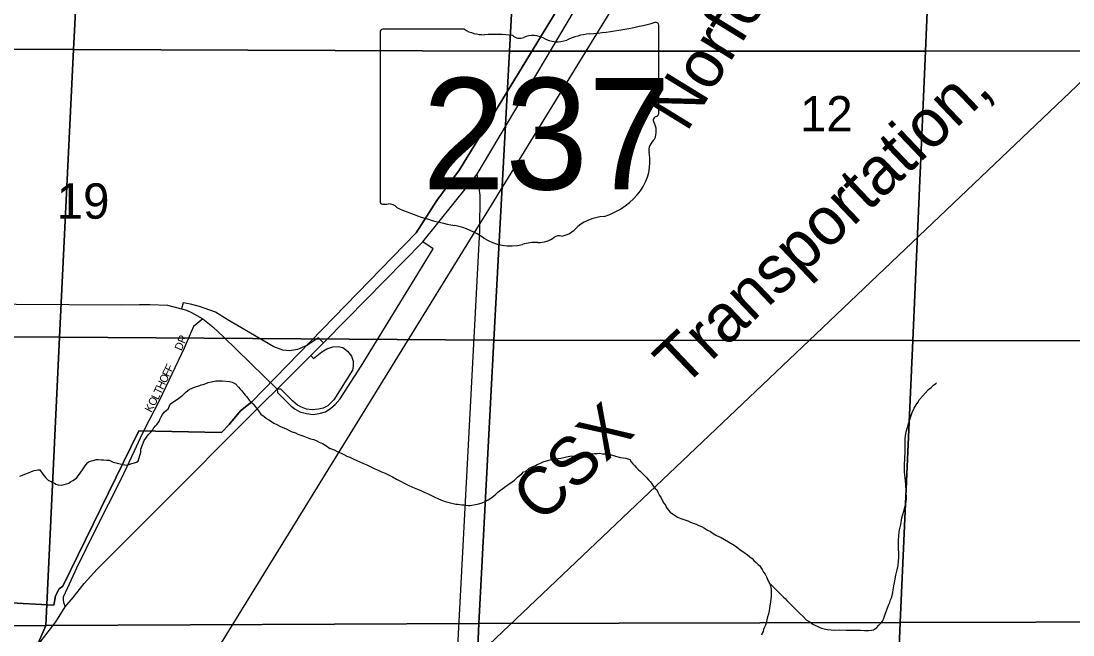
# Model space of a CAD drawing. Extents: x 2010165 to 2382125, y 1060529 to 1407316.
# Drawn here: x 2146157 to 2152727, y 1235609 to 1239445 of the extents above; entities that cross this region are included whole.
import ezdxf

# ---------------------------------------------------------------- set-up
doc = ezdxf.new("R2010")
doc.units = 0
for name, color, linetype in [('GM_X_City_Street', 7, 'Continuous'), ('GM_X_City_Street_Text', 7, 'Continuous'), ('GM_X_Corporation', 7, 'Continuous'), ('GM_X_Interchange_Ramps', 7, 'Continuous'), ('GM_X_Minor_River', 7, 'Continuous'), ('GM_X_Rail_Line', 7, 'Continuous'), ('GM_X_Rail_Line_Text', 7, 'Continuous'), ('GM_X_Section', 7, 'Continuous'), ('GM_X_Section_Text', 7, 'Continuous'), ('GM_X_State_Location', 7, 'Continuous'), ('GM_X_State_Route', 7, 'Continuous'), ('GM_X_State_Shield', 7, 'Continuous')]:
    doc.layers.add(name, color=color, linetype=linetype)

msp = doc.modelspace()

# ---------------------------------------------------------------- linework, layer by layer
at = {"layer": 'GM_X_City_Street'}
for points in [[(2148879.3, 1235417.3), (2149023.3, 1238135.7), (2149024.9, 1238357.3), (2149006, 1238487.7)], [(2144660.8, 1237692.8), (2145141.7, 1237682.9), (2146781.9, 1237671), (2146895.9, 1237673.3)], [(2146895.9, 1237673.3), (2146961.2, 1237674.6), (2147072.4, 1237669.7), (2147159, 1237647.3), (2147190.7, 1237637.5), (2147221, 1237624.8), (2147291.5, 1237584.5), (2147355.1, 1237533.5), (2147421.7, 1237471.6), (2147756.2, 1237145.5)], [(2147291.5, 1237584.5), (2147235.1, 1237535.5), (2147220.5, 1237503.5), (2147176.8, 1237401.6), (2147021.4, 1237075.5), (2146924.8, 1236885.7)], [(2146924.8, 1236885.7), (2146900.5, 1236837.9), (2146863.8, 1236758.1), (2146781.7, 1236585.3), (2146622, 1236267.8), (2146503.8, 1236026.5), (2146446.8, 1235902.8), (2146420.4, 1235844.7), (2146419.9, 1235826.8), (2146421.8, 1235814.4), (2146433.4, 1235784.8)]]:
    msp.add_lwpolyline(points, dxfattribs=at)
at = {"layer": 'GM_X_Corporation'}
for points in [[(2146055.1, 1235811.6), (2146361.7, 1235795.5), (2146372.7, 1235852.5), (2146394.6, 1235897.4), (2146419, 1235913.2), (2146892.4, 1236883.9), (2147408.3, 1236874.9), (2147457.8, 1236924.4), (2147528.5, 1237008.7), (2147599.3, 1237065.9), (2148624.8, 1238120.8), (2148753, 1238322.8), (2148895.2, 1238514.3), (2151697.2, 1243110.1)], [(2151697.2, 1243110.1), (2148895.2, 1238514.3), (2148753, 1238322.8), (2148624.8, 1238120.8), (2147599.3, 1237065.9), (2147528.5, 1237008.7), (2147457.8, 1236924.4), (2147408.3, 1236874.9), (2146892.4, 1236883.9), (2146419, 1235913.2), (2146394.6, 1235897.4), (2146372.7, 1235852.5), (2146361.7, 1235795.5), (2146055.1, 1235811.6)]]:
    msp.add_lwpolyline(points, dxfattribs=at)
at = {"layer": 'GM_X_Interchange_Ramps'}
for points in [[(2147756.2, 1237145.5), (2147758.3, 1237123.3), (2147843.4, 1237039.4), (2147869.9, 1237019.3), (2147899, 1237002.1), (2147940.3, 1236992), (2147981.5, 1236987.3), (2148019.8, 1236993.6), (2148059.4, 1237004), (2148091.8, 1237026.6), (2148118.7, 1237049.1), (2148149.5, 1237084), (2148174.8, 1237124.2), (2148281, 1237288.2), (2148730.9, 1238021), (2148667.3, 1238066.4)], [(2148045.6, 1237434.2), (2148015.3, 1237465.6), (2147941.1, 1237417.2), (2147884.1, 1237393.5), (2147833.9, 1237384.7), (2147791.2, 1237387.7), (2147736.5, 1237409.9), (2147444.1, 1237580.3), (2147371.3, 1237625.4), (2147272.1, 1237660.6), (2147215.3, 1237676.4), (2147169.3, 1237683.7), (2147159, 1237647.3)], [(2147966.1, 1237354.9), (2147983.9, 1237337), (2148036.6, 1237377.8), (2148067.7, 1237396.2), (2148104.4, 1237409.3), (2148138.7, 1237411.4), (2148167.6, 1237405.1), (2148196.9, 1237382.4), (2148220.8, 1237351.4), (2148231, 1237320), (2148231.7, 1237287.2), (2148228.1, 1237263.8), (2148111.3, 1237077.7), (2148073.7, 1237041.3), (2148043.8, 1237027), (2148015.2, 1237019.5), (2147975.5, 1237014.6), (2147939.8, 1237019.4), (2147909.3, 1237032.5), (2147883, 1237044.3), (2147852.3, 1237071), (2147778.7, 1237143.7), (2147756.2, 1237145.5)]]:
    msp.add_lwpolyline(points, dxfattribs=at)
at = {"layer": 'GM_X_Minor_River'}
for points in [[(2147139.9, 1237086), (2147153.8, 1237096.3), (2147163.7, 1237102.5), (2147179.4, 1237118.8), (2147189.3, 1237129.1), (2147207.1, 1237143.5), (2147229, 1237153.9), (2147246.9, 1237160.3), (2147260.9, 1237162.6), (2147272.9, 1237166.8), (2147282.8, 1237171), (2147294.8, 1237173.2), (2147310.8, 1237179.6), (2147326.7, 1237185.9), (2147346.7, 1237190.3), (2147372.6, 1237196.8), (2147392.7, 1237197.2), (2147414.8, 1237197.6), (2147459, 1237192.4), (2147475.1, 1237188.7), (2147487.3, 1237182.9), (2147497.4, 1237177.1), (2147515.9, 1237157.4), (2147526.1, 1237145.6), (2147536.4, 1237133.7), (2147548.7, 1237117.9), (2147556.9, 1237108), (2147565.1, 1237098.1), (2147573.3, 1237088.3), (2147581.6, 1237076.4), (2147591.8, 1237066.6), (2147608.1, 1237050.8), (2147616.4, 1237038.9), (2147626.7, 1237025.1), (2147641, 1237009.3), (2147655.4, 1236989.5), (2147675.8, 1236973.8), (2147690.1, 1236962.1), (2147704.3, 1236952.3), (2147720.5, 1236942.6), (2147736.8, 1236932.9), (2147755, 1236923.2), (2147773.2, 1236913.5), (2147791.4, 1236905.8), (2147809.6, 1236898.1), (2147825.8, 1236890.4), (2147844.1, 1236880.7), (2147870.3, 1236871.2), (2147886.5, 1236863.5), (2147904.7, 1236857.8), (2147922.9, 1236850.1), (2147943.1, 1236842.5), (2147965.3, 1236834.9), (2147985.5, 1236829.3), (2148003.7, 1236821.6), (2148019.9, 1236813.9), (2148040.1, 1236804.2), (2148060.4, 1236792.6), (2148082.8, 1236776.9), (2148113.1, 1236765.5), (2148135.4, 1236753.9), (2148155.6, 1236744.2), (2148173.8, 1236736.6), (2148192.1, 1236726.9), (2148210.3, 1236719.2), (2148230.5, 1236709.5), (2148295.3, 1236680.7), (2148317.5, 1236671.1), (2148345.9, 1236657.6), (2148366.1, 1236647.9), (2148388.4, 1236638.3), (2148408.6, 1236628.7), (2148430.9, 1236619.1), (2148455.2, 1236607.5), (2148477.5, 1236595.9), (2148501.8, 1236582.3), (2148526.1, 1236570.7), (2148550.4, 1236557.1), (2148574.7, 1236545.6), (2148601.1, 1236532), (2148633.4, 1236520.6), (2148657.7, 1236509), (2148679.9, 1236499.4), (2148700.2, 1236489.8), (2148720.4, 1236480.1), (2148740.7, 1236470.5), (2148760.9, 1236460.8), (2148783.2, 1236451.2), (2148805.4, 1236443.6), (2148823.6, 1236437.9), (2148837.7, 1236434.2), (2148855.8, 1236430.5), (2148871.9, 1236426.8), (2148886, 1236425.1), (2148898.1, 1236423.3), (2148910.1, 1236421.5), (2148924.2, 1236421.8), (2148934.3, 1236420), (2148952.4, 1236418.3), (2148962.4, 1236418.5), (2148972.4, 1236420.7)], [(2150831.6, 1235932.6), (2150895, 1235869.6), (2150907.3, 1235857.8), (2150919.5, 1235846), (2150929.8, 1235836.1), (2150940, 1235824.3), (2150954.3, 1235810.5), (2150968.6, 1235794.7), (2150987, 1235777), (2151003.4, 1235761.3), (2151023.8, 1235741.6), (2151042.2, 1235723.9), (2151060.6, 1235704.2), (2151083, 1235690.6), (2151101.3, 1235676.9), (2151115.5, 1235669.1), (2151129.6, 1235663.3), (2151141.8, 1235657.6), (2151155.9, 1235651.8), (2151174.1, 1235646.1), (2151194.2, 1235642.5), (2151216.3, 1235640.9), (2151238.4, 1235639.3), (2151270.5, 1235640), (2151312.7, 1235638.8), (2151344.8, 1235639.4), (2151374.9, 1235637.9), (2151401, 1235638.4), (2151425.1, 1235636.9), (2151449.2, 1235637.4), (2151469.2, 1235637.8), (2151481.2, 1235640), (2151501, 1235654.4), (2151514.8, 1235670.7), (2151528.5, 1235685.1), (2151538.4, 1235695.3), (2151544.2, 1235707.4), (2151551.8, 1235731.6), (2151574.7, 1235794.3), (2151582.4, 1235812.5), (2151588.1, 1235828.7), (2151593.9, 1235840.8), (2151597.6, 1235854.9), (2151601.3, 1235875.1), (2151605, 1235891.2), (2151608.6, 1235915.3), (2151614, 1235947.6), (2151621.4, 1235981.8), (2151628.8, 1236016.1), (2151634.3, 1236042.3), (2151637.8, 1236068.4), (2151639.4, 1236094.5), (2151638.9, 1236118.6), (2151638.4, 1236148.7), (2151637.5, 1236194.8), (2151638.8, 1236233), (2151644.2, 1236265.2), (2151651.6, 1236299.5), (2151658.9, 1236339.8), (2151670.2, 1236382.1), (2151679.6, 1236414.4), (2151685.2, 1236438.6), (2151686.7, 1236464.7), (2151686, 1236502.8), (2151683.1, 1236548.9), (2151678.3, 1236591), (2151675.6, 1236629.1), (2151675.3, 1236645.1), (2151675, 1236661.1), (2151674.6, 1236683.2), (2151676.3, 1236701.3), (2151677.9, 1236721.4), (2151679.5, 1236741.5), (2151679.1, 1236763.6), (2151678.7, 1236787.6), (2151678.2, 1236813.7), (2151679.9, 1236831.8), (2151681.4, 1236855.9), (2151685, 1236878.1), (2151692.6, 1236904.3), (2151700.2, 1236928.5), (2151705.8, 1236948.7), (2151713.4, 1236972.9), (2151722.9, 1236999.2), (2151734.5, 1237025.5), (2151748.2, 1237045.8), (2151757.9, 1237062.1), (2151769.6, 1237080.4), (2151824.6, 1237141.6), (2151840.4, 1237156), (2151856.2, 1237170.3), (2151870.1, 1237180.6), (2151874.4, 1237183.6)], [(2146149.5, 1236601.4), (2146165.5, 1236607.8), (2146181.4, 1236614.1), (2146203.3, 1236622.5), (2146223.2, 1236630.9), (2146239.2, 1236637.3), (2146249.2, 1236639.5), (2146261.2, 1236641.7), (2146275.2, 1236640), (2146293.8, 1236614.2), (2146310.2, 1236592.5), (2146328.6, 1236574.8), (2146342.8, 1236569), (2146355, 1236561.2), (2146365.1, 1236557.4), (2146375.2, 1236551.6), (2146389.3, 1236547.8), (2146407.5, 1236544.2), (2146425.4, 1236548.5), (2146441.4, 1236552.8), (2146455.4, 1236557.1), (2146465.3, 1236565.3), (2146481.2, 1236573.7), (2146503, 1236588.1), (2146540.1, 1236641), (2146553.8, 1236659.3), (2146563.6, 1236673.6), (2146571.4, 1236683.8), (2146583.3, 1236692), (2146597.3, 1236696.3), (2146607.3, 1236698.5), (2146625.2, 1236704.9), (2146639.3, 1236705.1), (2146659.4, 1236703.5), (2146671.4, 1236703.8), (2146693.5, 1236700.1), (2146707.6, 1236700.4), (2146731.9, 1236688.8), (2146760.1, 1236681.4), (2146784.3, 1236675.8), (2146804.4, 1236672.2), (2146818.5, 1236670.4), (2146848.4, 1236681.1), (2146866.4, 1236685.4), (2146878.4, 1236689.6), (2146888.3, 1236693.9), (2146905.3, 1236750.4), (2146905, 1236770.4), (2146926, 1236823), (2146951.5, 1236859.6), (2146967.2, 1236876), (2146977, 1236888.2), (2146986.8, 1236902.4), (2146996.6, 1236914.7), (2147004.4, 1236924.8), (2147020.1, 1236943.2), (2147023.9, 1236955.3), (2147031.7, 1236971.5), (2147041.4, 1236985.8), (2147051.2, 1237002), (2147067, 1237016.4), (2147076.9, 1237020.6), (2147088.4, 1237050.9), (2147118.1, 1237071.5), (2147139.9, 1237086)], [(2148972.4, 1236420.7), (2148996.4, 1236423.2), (2149016.4, 1236427.6), (2149036.3, 1236434), (2149056.2, 1236442.4), (2149074.1, 1236452.8), (2149092, 1236463.2), (2149107.8, 1236475.5), (2149121.6, 1236487.8), (2149135.4, 1236500.1), (2149151.2, 1236514.5), (2149167.1, 1236524.8), (2149184.9, 1236539.2), (2149196.8, 1236547.4), (2149224.5, 1236566), (2149238.4, 1236576.3), (2149258.1, 1236594.8), (2149270, 1236605), (2149283.8, 1236615.3), (2149295.6, 1236627.6), (2149307.6, 1236629.8), (2149331.3, 1236650.4), (2149349.2, 1236658.7), (2149359.2, 1236662.9), (2149371.2, 1236667.2), (2149381.1, 1236673.4), (2149401, 1236681.8), (2149418.9, 1236690.2), (2149438.8, 1236696.6), (2149460.8, 1236703), (2149484.8, 1236709.5), (2149510.8, 1236712), (2149528.8, 1236714.3), (2149538.8, 1236716.6), (2149562.8, 1236721), (2149584.8, 1236725.4), (2149612.8, 1236728), (2149648.9, 1236732.7), (2149664.9, 1236735), (2149680.9, 1236735.3), (2149697, 1236737.6), (2149717, 1236740), (2149739, 1236742.5), (2149755.1, 1236742.8), (2149769.1, 1236745), (2149789.2, 1236741.4), (2149803.3, 1236739.7), (2149815.3, 1236739.9), (2149829.4, 1236738.2), (2149869.7, 1236726.9), (2149902, 1236717.5), (2149934.2, 1236714.1), (2149946.3, 1236710.3), (2149958.4, 1236704.5), (2149968.7, 1236690.7), (2149979, 1236678.8), (2149989.2, 1236667), (2150001.5, 1236653.2), (2150013.8, 1236641.4), (2150024, 1236631.5), (2150038.3, 1236617.8), (2150050.6, 1236605.9), (2150062.9, 1236592.1), (2150075.2, 1236578.3), (2150087.4, 1236566.5), (2150097.7, 1236552.7), (2150108, 1236536.8), (2150118.3, 1236525), (2150128.5, 1236515.1), (2150134.8, 1236501.2), (2150145.2, 1236481.3), (2150155.5, 1236465.5), (2150163.9, 1236447.6), (2150172.2, 1236431.7), (2150182.5, 1236419.8), (2150188.7, 1236405.9), (2150199.1, 1236390), (2150211.4, 1236376.2), (2150225.6, 1236366.5), (2150241.9, 1236354.8), (2150258.1, 1236345), (2150278.3, 1236337.4), (2150302.6, 1236327.8), (2150320.7, 1236322.1), (2150338.9, 1236314.5), (2150355.1, 1236306.7), (2150373.3, 1236301.1), (2150389.5, 1236293.3), (2150407.7, 1236285.7), (2150425.9, 1236276), (2150444.2, 1236264.3), (2150462.5, 1236254.6), (2150480.7, 1236242.9), (2150501, 1236229.3), (2150529.4, 1236217.8), (2150549.6, 1236206.1), (2150600.4, 1236177), (2150616.6, 1236165.3), (2150632.9, 1236153.5), (2150649.2, 1236141.8), (2150665.4, 1236130.1)], [(2150665.4, 1236130.1), (2150679.7, 1236120.3), (2150691.8, 1236112.5), (2150708.2, 1236096.8), (2150722.4, 1236087), (2150734.7, 1236073.2), (2150749, 1236061.4), (2150761.2, 1236049.6), (2150771.5, 1236039.8), (2150777.7, 1236029.9), (2150785.9, 1236018), (2150794.2, 1236002.1), (2150804.5, 1235988.2), (2150812.8, 1235972.3), (2150821.3, 1235950.4), (2150831.6, 1235932.6), (2150837.9, 1235918.6), (2150840.2, 1235904.6), (2150842.4, 1235892.6), (2150842.6, 1235880.6), (2150842.9, 1235866.6), (2150841.2, 1235850.5), (2150839.5, 1235832.4), (2150837.8, 1235818.3), (2150836.1, 1235802.2), (2150834.3, 1235790.1), (2150832.5, 1235776.1), (2150828.8, 1235759.9), (2150825.2, 1235739.8), (2150819.5, 1235721.6), (2150815.8, 1235703.5), (2150810.1, 1235685.3), (2150806.4, 1235669.2), (2150800.6, 1235657.1), (2150794.9, 1235642.9), (2150791.1, 1235630.8), (2150785.2, 1235620.6), (2150781.5, 1235608.5)]]:
    msp.add_lwpolyline(points, dxfattribs=at)
at = {"layer": 'GM_X_Rail_Line'}
for points in [[(2148913.3, 1235390.1), (2151121.4, 1237488.2), (2153352.2, 1239614.8), (2153929.8, 1240167.4), (2154543.4, 1240751.8), (2155500, 1241661.6), (2155854.6, 1241999.2), (2157533.9, 1243588.4), (2158657.3, 1244653.5), (2159470.9, 1245426.4), (2160143.4, 1246061.6), (2160845.1, 1246725.4), (2160959.7, 1246827.7)], [(2149044.8, 1238213.7), (2150890.9, 1241216.3), (2152083.2, 1243172), (2153583.7, 1245507.5), (2154044.4, 1246339), (2154268.6, 1246712.7)], [(2149019.9, 1238173.1), (2149044.8, 1238213.7)], [(2144106.6, 1231241.8), (2144229.6, 1231335.2), (2144420.6, 1231469.2), (2144593.9, 1231598.3), (2144768.9, 1231732.5), (2144893, 1231824.9), (2145010.5, 1231928.2), (2145104.6, 1232021.5), (2145218.7, 1232148.2), (2145340.4, 1232286.4), (2145444.5, 1232419.7), (2145531.1, 1232538), (2145627.8, 1232682.2), (2145736.9, 1232852.9), (2146031, 1233329.5), (2146368.4, 1233874.3), (2146737, 1234469.9), (2146943.7, 1234810.9), (2147365.6, 1235489.3), (2147948.7, 1236435), (2148494.7, 1237318.9), (2149019.9, 1238173.1)]]:
    msp.add_lwpolyline(points, dxfattribs=at)
at = {"layer": 'GM_X_Section'}
for points in [[(2146579.7, 1241102), (2146484.2, 1239266.4), (2143983.7, 1239275.5), (2144057.8, 1241124.1)], [(2149305.2, 1241078.2), (2149207.4, 1239256.6), (2146484.2, 1239266.4), (2146579.7, 1241102)], [(2151882.3, 1241078.6), (2151805.6, 1239257.3), (2149207.4, 1239256.6), (2149305.2, 1241078.2)], [(2154452.9, 1241078.9), (2154353.5, 1239257.9), (2151805.6, 1239257.3), (2151882.3, 1241078.6)], [(2146484.2, 1239266.4), (2146397.7, 1237469.6), (2143912, 1237485.9), (2143946.6, 1238350.5), (2143983.7, 1239275.5)], [(2149207.4, 1239256.6), (2149110.6, 1237451.9), (2146397.7, 1237469.6), (2146484.2, 1239266.4)], [(2151805.6, 1239257.3), (2151726.1, 1237448.4), (2149110.6, 1237451.9), (2149207.4, 1239256.6)], [(2154353.5, 1239257.9), (2154270.7, 1237444.9), (2151726.1, 1237448.4), (2151805.6, 1239257.3)], [(2143912, 1237485.9), (2146397.7, 1237469.6), (2146311, 1235667.1), (2143838.9, 1235662.2)], [(2146397.7, 1237469.6), (2149110.6, 1237451.9), (2149015.6, 1235680.2), (2146311, 1235667.1)], [(2149110.6, 1237451.9), (2151726.1, 1237448.4), (2151648.7, 1235687), (2149015.6, 1235680.2)], [(2151726.1, 1237448.4), (2154270.7, 1237444.9), (2154191.2, 1235693.4), (2151648.7, 1235687)], [(2143838.9, 1235662.2), (2146311, 1235667.1), (2146173.7, 1235349.6), (2146170.5, 1233914.6), (2143762.7, 1233892)], [(2146311, 1235667.1), (2149015.6, 1235680.2), (2148942, 1233922.4), (2147000.9, 1233922.4), (2146170.5, 1233914.6), (2146173.7, 1235349.6)], [(2149015.6, 1235680.2), (2151648.7, 1235687), (2151574.1, 1233919.6), (2148942, 1233922.4)], [(2151648.7, 1235687), (2154191.2, 1235693.4), (2154110.6, 1233916.9), (2151574.1, 1233919.6)]]:
    msp.add_lwpolyline(points, close=True, dxfattribs=at)
at = {"layer": 'GM_X_State_Route'}
for points in [[(2148947, 1238414.3), (2149006, 1238487.7), (2149803.7, 1239832.6), (2149947.2, 1240052.4)], [(2148191.9, 1237583), (2148667.3, 1238066.4), (2148947, 1238414.3)], [(2148045.6, 1237434.2), (2148191.9, 1237583)], [(2147669.4, 1237058.6), (2147756.2, 1237145.5), (2147966.1, 1237354.9), (2148045.6, 1237434.2)], [(2146965.8, 1236353.9), (2147669.4, 1237058.6)], [(2146214.3, 1235483.3), (2146373.6, 1235691), (2146433.4, 1235784.8), (2146482.9, 1235842.1), (2146551.4, 1235931), (2146632.3, 1236020), (2146965.8, 1236353.9)]]:
    msp.add_lwpolyline(points, dxfattribs=at)
at = {"layer": 'GM_X_State_Shield'}
for p, q in [((2148926.3, 1239393.4), (2148416.7, 1239393.4)), ((2150139.8, 1238866.8), (2150139.8, 1239419.5)), ((2148399.6, 1239375.2), (2148399.6, 1238318.5)), ((2150139.6, 1238866.9), (2150139.8, 1238866.8))]:
    msp.add_line(p, q, dxfattribs=at)
for centre, major_axis, start_param, end_param in [((2148419.5, 1239377.4), (20.2, 0), 1.712693, 3.28349), ((2149047.7, 1239516), (195.5, 0), 4.042523, 4.731795), ((2149519.9, 1240833.9), (1845.5, 0), 4.814394, 5.042369), ((2150120.5, 1239421.8), (19.4, 0), 6.141152, 7.989035), ((2149112.5, 1238800.2), (702, 0), 1.404758, 1.657858), ((2149271.9, 1239382.9), (56.4, 0), 3.836095, 5.185415), ((2149354.7, 1239260.8), (117.3, 0), 0.950623, 2.079405), ((2149506.1, 1239428.3), (141.1, 0), 4.081561, 5.145723), ((2149755.3, 1239070.6), (371.3, 0), 1.699011, 2.107814), ((2150119.1, 1238864.7), (20.7, 0), 5.05454, 6.418171), ((2150135.3, 1238826.2), (30, 0), 1.883978, 3.671073), ((2149944.5, 1238756.4), (180, 0), 5.934695, 6.695948), ((2150209.2, 1238635.5), (130.9, 0), 2.387724, 3.262537), ((2149623.3, 1238565.2), (461.6, 0), 5.101752, 6.440018), ((2148419.7, 1238316.2), (20.3, 0), 3.00124, 4.508301), ((2148422.8, 1238424.3), (155.2, 0), 4.665946, 4.897461), ((2148454.5, 1238257.6), (56, 0), 0.519207, 1.627899), ((2149161.1, 1239206.9), (1332.7, 0), 4.195997, 4.488961), ((2149817.9, 1238021.9), (252.8, 0), 1.647645, 2.488434), ((2148763.8, 1237843.8), (417, 0), 0.823519, 1.323587), ((2149497.6, 1238216.1), (149.1, 0), 4.937069, 5.64225), ((2149214.8, 1238252.3), (264.6, 0), 4.026481, 4.996735), ((2149387, 1238173.2), (141, 0), 4.691044, 5.507374), ((2149514.5, 1238070.9), (39.7, 0), 1.147584, 2.315152), ((2149367.6, 1237887), (217.4, 0), 1.495662, 1.94098)]:
    msp.add_ellipse(centre, major_axis=major_axis, ratio=0.8, start_param=start_param, end_param=end_param, dxfattribs=at)

# ---------------------------------------------------------------- texts
at = {"layer": 'GM_X_City_Street_Text'}
for s, rotation, p in [('DR', 67.1694, (2147159.1, 1237381.2)), ('F', 64.41926, (2147096.1, 1237249.4)), ('O', 64.39288, (2147061.9, 1237177.9)), ('F', 64.37573, (2147080.9, 1237217.6)), ('T', 64.38503, (2147027.6, 1237106.5)), ('H', 64.40742, (2147042.9, 1237138.3)), ('O', 62.47302, (2146990.9, 1237034.3)), ('L', 63.74534, (2147011.8, 1237074.4)), ('K', 62.29133, (2146970.4, 1236995.2))]:
    msp.add_text(s, height=50, rotation=rotation, dxfattribs=at).set_placement(p)
at = {"layer": 'GM_X_Rail_Line_Text'}
for s, rotation, p in [('Norfolk', 58.39221, (2150314.6, 1238744.2)), ('Transportation,', 43.59412, (2150289, 1237145.7)), ('CSX', 43.68453, (2149405.4, 1236299.2))]:
    msp.add_text(s, height=299, rotation=rotation, dxfattribs=at).set_placement(p)
at = {"layer": 'GM_X_Section_Text'}
for s, p in [('12', (2151022.3, 1238754.9)), ('19', (2146380.3, 1238209.9))]:
    msp.add_text(s, height=221, rotation=0.00001, dxfattribs=at).set_placement(p)
at = {"layer": 'GM_X_State_Location'}
for s in ['s', 'r']:
    msp.add_text(s, height=1, dxfattribs=at).set_placement((2149250.1, 1238776.6))
msp.add_text('237', height=1, rotation=0.00001, dxfattribs=at).set_placement((2148897.1, 1238703.9))
at = {"layer": 'GM_X_State_Shield'}
msp.add_text('237', height=696.1, dxfattribs=at).set_placement((2148663.2, 1238393.1))

doc.saveas('drawing.dxf')
